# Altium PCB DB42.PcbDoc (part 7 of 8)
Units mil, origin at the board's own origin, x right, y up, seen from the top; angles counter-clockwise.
Board outline 3236.22 x 4456.69 mil, 8 copper layers (Top Layer, MidLayer1, MidLayer2, GND-Layer5, MidLayer3, VCC, MidLayer4, Bottom Layer), stack 62.194 mil thick; 214 components, 470 nets, 1802 pads, 1663 vias.
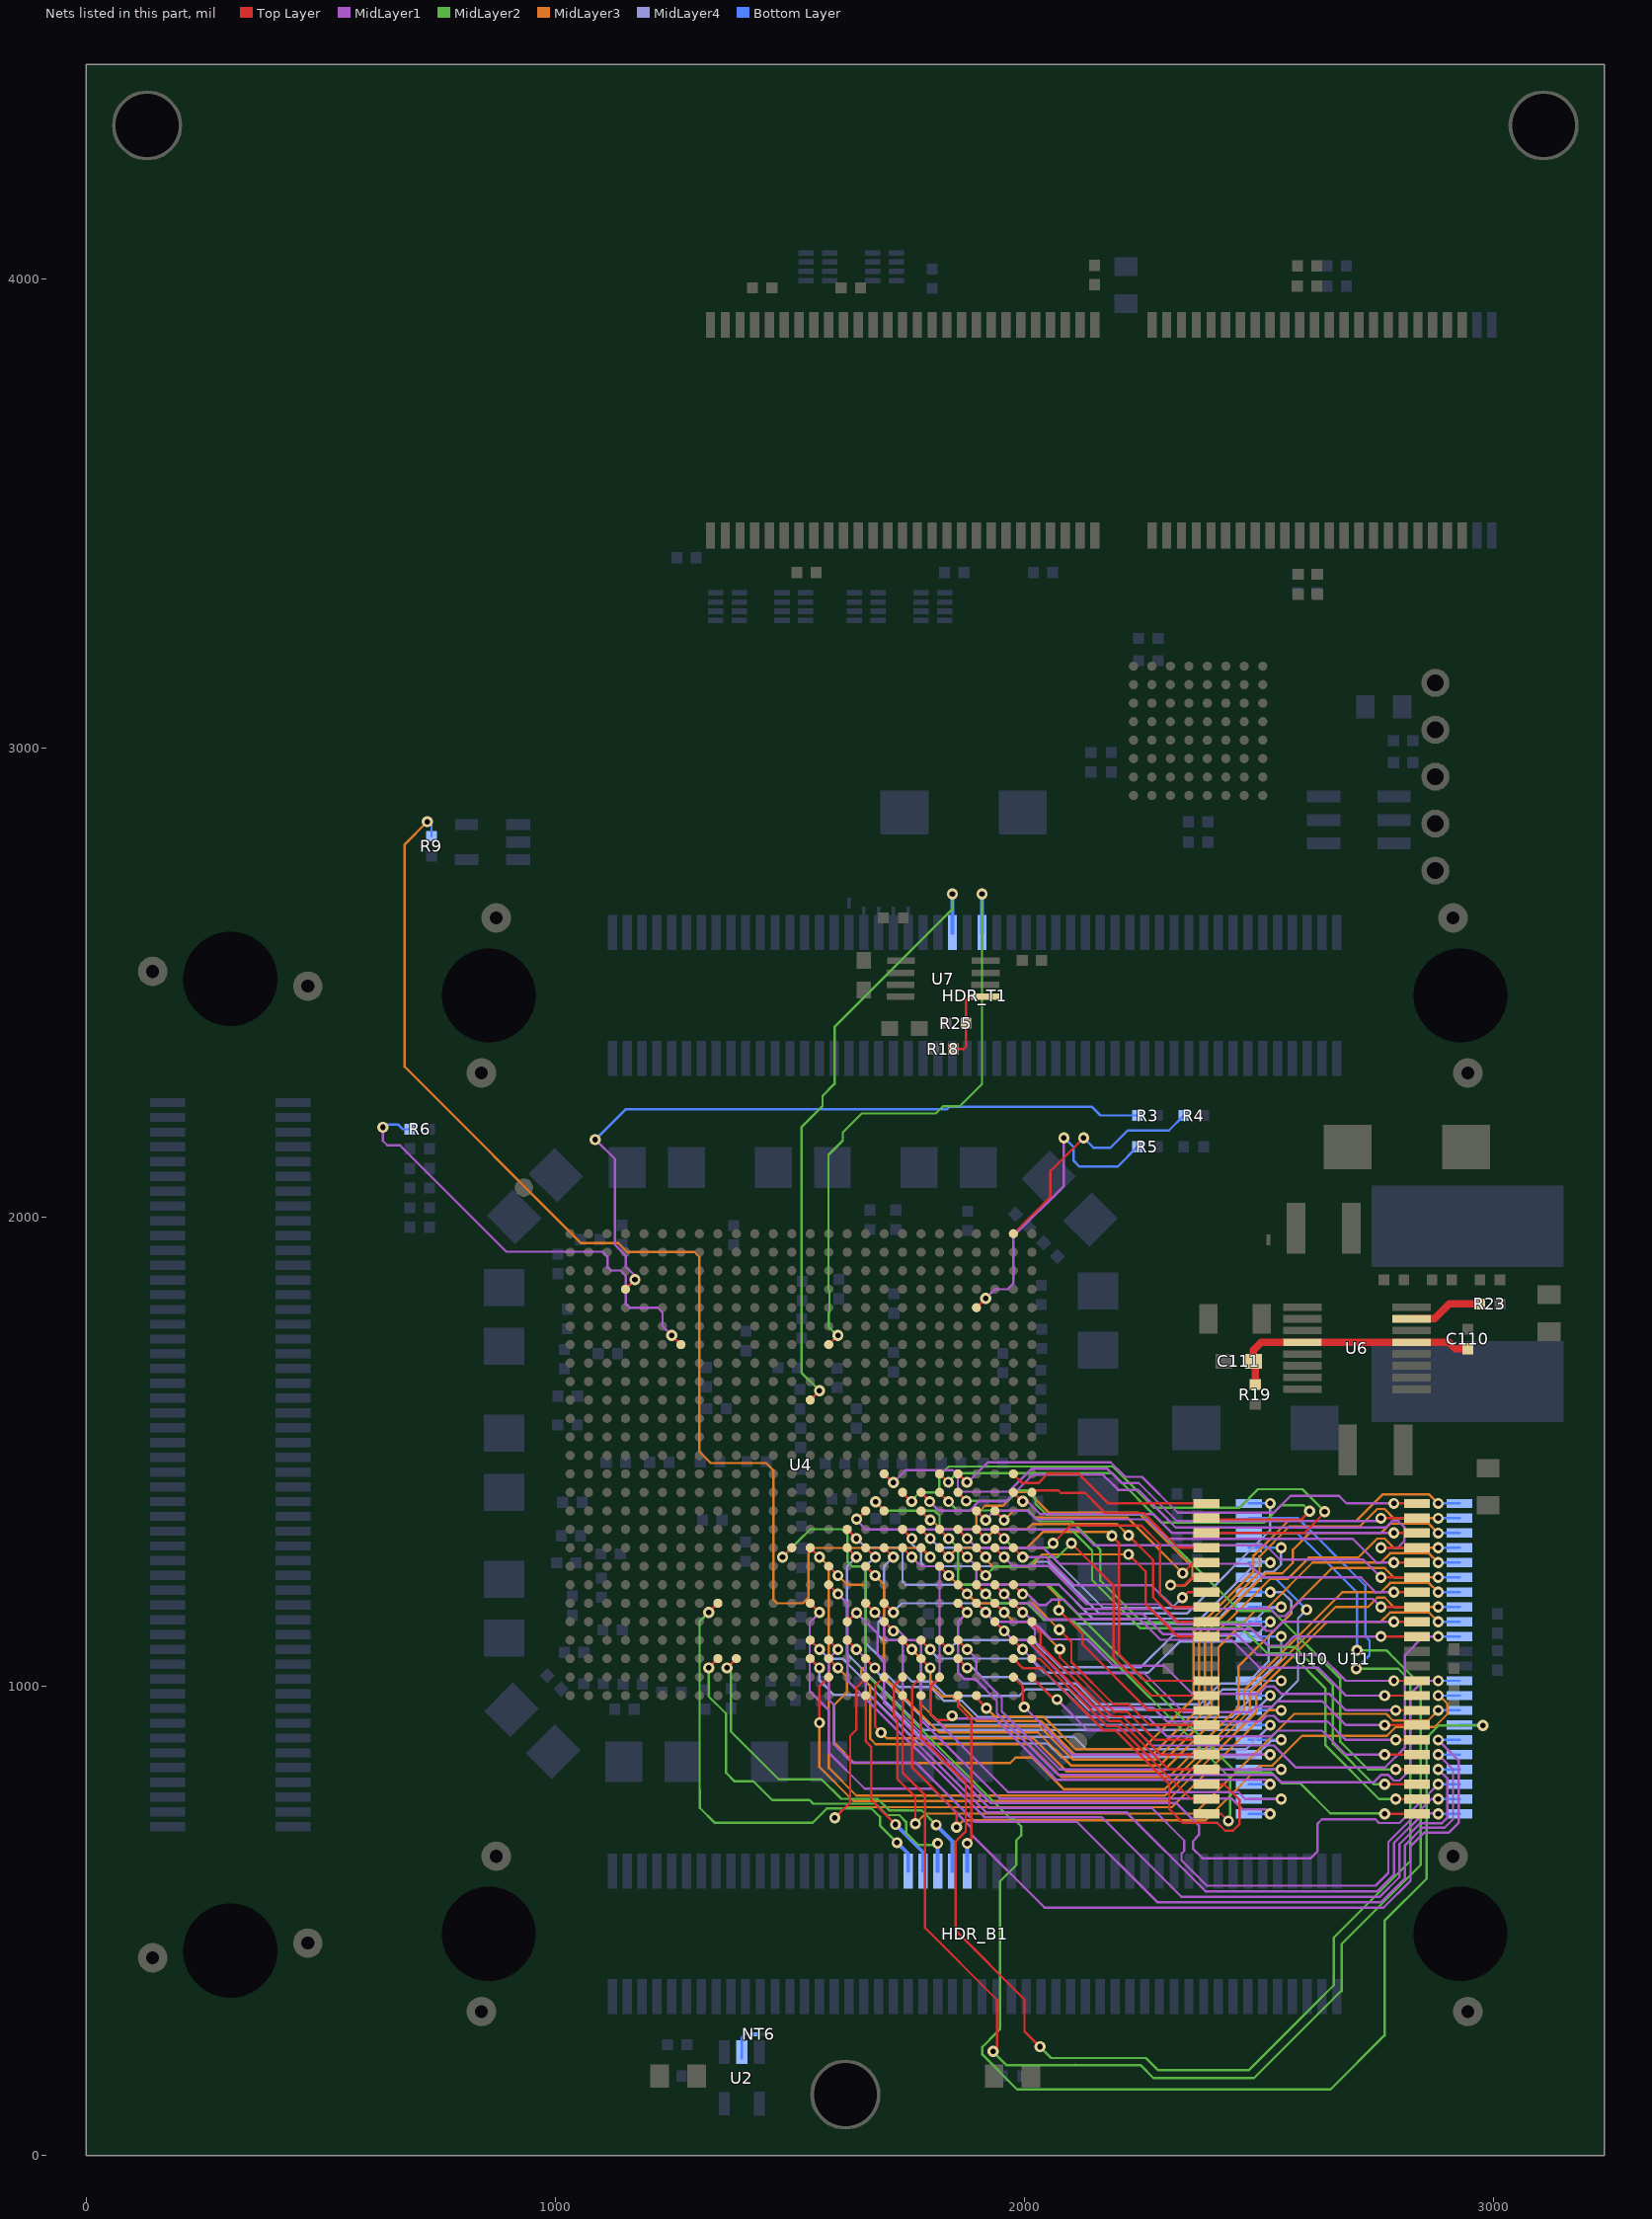
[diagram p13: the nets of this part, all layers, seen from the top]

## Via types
v1: diameter 23.62, hole 11.81, Top Layer to Bottom Layer, 1081 vias
v2: diameter 23.62, hole 11.81, Top Layer to Bottom Layer, tented both sides, 466 vias
v3: diameter 27.56, hole 15.75, Top Layer to Bottom Layer, 116 vias

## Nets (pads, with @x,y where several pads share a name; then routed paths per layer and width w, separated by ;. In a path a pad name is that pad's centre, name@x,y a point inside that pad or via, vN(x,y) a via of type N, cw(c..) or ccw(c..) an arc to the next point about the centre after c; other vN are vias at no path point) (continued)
SPI_MODE: HDR_T1.52 U4.G15 | length 1310.7
  Top Layer w5: U4.G15@1582.68,1728.35 v1(1602.36,1748.03)
  MidLayer2 w5: v1(1602.36,1748.03) 1600.52,1748.03 1592.34,1756.21 1583.05,1765.5 1583.05,1795.6 1584.24,1796.78 1584.24,1843.03 1582.3,1844.97 1582.3,2132.33 1612.78,2162.8 1612.78,2180.54 1653.12,2220.89 1811.05,2220.89 1826.28,2236.13 1861.72,2236.13 1868.9,2243.31 ; 1869.09,2243.11 1909.45,2283.47 v2(1909.45,2688.98)
  Bottom Layer w7.87: HDR_T1.52@1909.45,2606.3 v2(1909.45,2688.98)
SPI_SEL: HDR_T1.48 U4.K14 | length 1318.3
  Top Layer w5: U4.K14@1543.31,1610.24 v1(1562.99,1629.92)
  MidLayer2 w5: v1(1562.99,1629.92) 1525.2,1667.72 1525.2,2192.35 1569.44,2236.59 1569.44,2258.24 1595.06,2283.86 1595.06,2405.41 1846.46,2656.8 v2(1846.46,2688.98)
  Bottom Layer w7.87: HDR_T1.48@1846.46,2606.3 v2(1846.46,2688.98)
SRAM1_A0: U4.AB18 U11.1 | length 1130.6
  Top Layer w5: U4.AB18@1700.79,1137.8 v1(1720.47,1118.11)
  MidLayer1 w5: v1(1720.47,1118.11) 1732.28,1118.11 1751.97,1098.43 1768.11,1098.43 1779.15,1087.38 1779.15,928.72 1946.85,761.02 2441.14,761.02 2464.13,738.03 2513.94,738.03 v1(2523.62,728.35)
  Bottom Layer w5: U11.1@2478.44,728.34 v1(2523.62,728.35)
SRAM1_A1: U4.V19 U11.2 | length 1306.2
  Top Layer w5: U4.V19@1740.16,1295.28 v1(1759.84,1275.59)
  MidLayer1 w5: v1(1759.84,1275.59) 1779.53,1255.91 1812.2,1255.91 1818.9,1249.21 1818.9,1016.93 1799.7,997.74 1799.7,939.67 1964.96,774.41 2456.04,774.41 2470.61,759.84 v1(2547.24,759.84)
  Bottom Layer w5: U11.2@2478.44,759.83 v1(2547.24,759.84)
SRAM1_A2: U4.AE21 U11.3 | length 926
  Top Layer w5: U4.AE21@1818.9,1019.68 1818.9,1018.9 1799.13,999.13 1799.13,941.42 1812.49,928.06 1836.32,928.06 v1(1845.61,937.34)
  MidLayer1 w5: v1(1845.61,937.34) 1851.46,931.5 1936.63,931.5 2067.1,801.02 2513.94,801.02 v1(2523.62,791.34)
  Bottom Layer w5: U11.3@2478.44,791.33 v1(2523.62,791.34)
SRAM1_A3: U4.AC22 U11.4 | length 906.3
  Top Layer w5: U4.AC22@1858.27,1098.42 v1(1877.95,1078.74)
  MidLayer1 w5: v1(1877.95,1078.74) 1897.26,1059.43 1897.26,1029.53 1951.57,975.22 1951.57,946.46 2075.2,822.83 v1(2547.24,822.83)
  Bottom Layer w5: U11.4@2478.44,822.83 v1(2547.24,822.83)
SRAM1_A4: U4.AE25 U11.5 | length 684.7
  Top Layer w5: U4.AE25@1976.38,1019.68 1996.46,999.61 1996.46,959.06 v1(1999.61,955.91)
  MidLayer1 w5: v1(1999.61,955.91) 2101.18,854.33 v1(2523.62,854.33)
  Bottom Layer w5: U11.5@2478.44,854.32 v1(2523.62,854.33)
SRAM1_A5: U4.U16 U11.18 | length 1110.9
  Top Layer w5: U4.U16@1622.05,1334.65 v1(1641.73,1314.96)
  MidLayer4 w5: v1@1642.52,1314.96 1662.2,1295.28 1731.89,1295.28 1740.16,1287.01 1740.16,1223.23 1746.85,1216.54 2072.98,1216.54 2145.16,1144.35 2375.45,1144.35 2496.85,1265.75 v1@2521.85,1265.75
  Bottom Layer w5: U11.18@2478.44,1263.77 v1(2523.83,1263.77)
SRAM1_A6: U4.AA18 U11.19 | length 1037.2
  Top Layer w5: U4.AA18@1700.79,1177.17 v1(1720.47,1157.48)
  MidLayer4 w5: v1@1719.68,1158.27 1738.58,1177.17 2006.07,1177.17 2040.82,1142.42 ; 2040.82,1141.44 2096.9,1141.44 2104.78,1133.57 2403.91,1133.57 2420.64,1150.3 ; 2420.11,1150.82 2453.95,1184.66 2513.61,1244.32 2531.72,1244.32 2546.85,1259.45 v1@2546.85,1294.88
  Bottom Layer w5: U11.19@2478.44,1295.27 v1(2547.24,1295.28)
SRAM1_A7: U4.AF19 U11.20 | length 2986.5
  Top Layer w5: U4.AF19@1740.16,980.31 1740.16,815.75 1788.19,767.72 1788.19,485.04 1941.73,331.5 1941.73,230.71 v1(1933.07,222.05)
  MidLayer2 w5: v1@1932.28,222.44 1932.28,222.05 1932.28,221.65 1932.48,221.46 1961.02,192.91 2107.87,192.91 ; 2108.27,193.31 2107.87,192.91 ; 2675.98,350.39 2675.98,351.97 ; v1(2708.66,1076.77) 2771.26,1076.77 2788.34,1059.69 2844.49,1003.54 2844.49,825.98 ; 2844.09,826.38 2844.49,825.98 ; 2107.87,192.91 2247.24,192.91 2274.8,165.35 2489.37,165.35 2675.98,351.97 ; 2675.98,351.97 2675.98,450.79 2844.49,619.29 2844.49,825.98
  Bottom Layer w5: U11.20@2478.44,1326.76 2581.51,1326.76 2603.35,1304.92 ; 2603.54,1305.12 2708.66,1200 v1(2708.66,1076.77)
SRAM1_A8: U4.AF20 U11.21 | length 2934.3
  Top Layer w5: U4.AF20@1779.53,980.31 1779.53,890.55 1857.87,812.2 ; 1857.87,811.42 1872.44,796.85 ; 1872.83,796.85 1874.85,794.83 1874.85,690.6 1862.2,677.95 1853.54,669.29 1853.54,479.13 2000,332.68 2000,264.96 v1(2032.94,232.02)
  MidLayer2 w5: v1(2032.94,232.02) 2057.09,207.87 2258.66,207.87 2284.25,182.28 2478.74,182.28 2620.95,324.49 2659.45,362.99 2659.45,464.57 2822.44,627.56 2822.44,1011.45 2816.16,1017.73 2796.06,1037.8 v1(2707.09,1037.8)
  Bottom Layer w5: U11.21@2478.44,1358.26 2583.07,1358.27 2642.91,1298.43 2658.02,1283.32 2726.77,1214.57 2726.77,1106.69 2729.53,1103.94 2735.71,1097.75 2735.71,1066.42 v1(2707.09,1037.8)
SRAM1_A9: U4.U19 U11.22 | length 1061
  Top Layer w5: U4.U19@1740.16,1334.65 v1(1759.84,1314.96)
  MidLayer4 w5: v1@1759.84,1316.14 v1(1759.84,1314.96) 1759.84,1303.39 1779.53,1283.71 1779.53,1262.99 1786.61,1255.91 2014.57,1255.91 2024.09,1265.42 2049.2,1265.42 2159.45,1155.18 2346.12,1155.18 2523.23,1332.28 v1@2523.23,1389.15
  Bottom Layer w5: U11.22@2478.44,1389.75 v1(2523.83,1389.75)
SRAM1_A10: U4.AF23 U11.23 | length 1416.3
  Top Layer w5: U4.AF23@1897.64,980.31 1897.64,974.8 v1(1918.9,953.54)
  MidLayer3 w5: v1(1918.9,953.54) 1936.61,935.83 2039.83,935.83 2109.52,866.14 2251.58,866.14 2360.63,975.2 2360.63,1117.29 2488.04,1244.7 2488.04,1278.3 2562.4,1352.66 2707.38,1352.66 2764.17,1409.45 2862.2,1409.45 v1(2881.9,1389.75)
  Bottom Layer w5: v1(2881.9,1389.75) U11.23@2927.25,1389.75
SRAM1_A11: U4.AD20 U11.24 | length 1592.3
  Top Layer w5: U4.AD20@1779.53,1059.05 v1(1799.21,1039.37)
  MidLayer3 w5: v1(1799.21,1039.37) 1799.21,1003.54 1824.02,978.74 1845.67,978.74 1898.58,925.83 2035.69,925.83 2105.37,856.14 2106.56,856.14 2107.98,854.72 2273.62,854.72 2372.05,953.15 2372.05,1114.57 2500.79,1243.31 2500.79,1276.38 ; 2500.63,1276.54 2564.64,1340.55 2714.57,1340.55 2751.97,1377.95 2767.72,1377.95 2787.41,1358.26 v1(2881.9,1358.26)
  Bottom Layer w5: v1(2881.9,1358.26) U11.24@2927.25,1358.26
SRAM1_A12: U4.AC19 U11.25 | length 1677.4
  Top Layer w5: U4.AC19@1740.16,1098.42 v1(1759.84,1078.74)
  MidLayer3 w5: v1(1759.84,1078.74) 1761.42,1077.17 1779.53,1059.06 1779.53,962 1827.35,914.17 2033.2,914.17 2101.23,846.14 2101.86,846.14 2103.91,844.09 2280.71,844.09 2384.65,948.03 2384.65,1111.02 2514.57,1240.94 2550,1240.94 2572.05,1262.99 2572.05,1290.95 2607.48,1326.38 2759.45,1326.38 2779.53,1346.46 2862.2,1346.46 v1(2881.9,1326.76)
  Bottom Layer w5: v1(2881.9,1326.76) U11.25@2927.25,1326.76
SRAM1_A13: U4.W17 U11.26 | length 1862.4
  Top Layer w5: U4.W17@1661.42,1255.91 v1(1681.5,1236.22)
  MidLayer3 w5: v1@1679.92,1237.01 1680.31,1237.01 1681.3,1236.02 1700.79,1216.54 1700.79,1019 1817.82,901.97 2029.03,901.97 2099.9,831.1 2287.4,831.1 2398.82,942.52 2398.82,1103.94 2523.62,1228.74 2560.63,1228.74 2605.91,1274.02 2711.02,1274.02 2751.97,1314.96 2767.72,1314.96 2787.41,1295.27 v1(2881.9,1295.27)
  Bottom Layer w5: v1(2881.9,1295.27) U11.26@2927.25,1295.27
SRAM1_A14: U4.AE18 U11.27 | length 1685.3
  Top Layer w5: v1(1694.45,901.34) 1681.46,914.34 1681.46,1000.71 1700.43,1019.68 U4.AE18@1700.79,1019.68
  MidLayer3 w5: v1(1694.45,901.34) 1706.28,889.51 2018.49,889.51 2089.1,818.9 2295.67,818.9 2413.58,936.81 2413.58,1083.27 2496.46,1166.14 2516.54,1166.14 2614.17,1263.78 2759.84,1263.78 2779.53,1283.46 2862.2,1283.46 v1(2881.9,1263.77)
  Bottom Layer w5: v1(2881.9,1263.77) U11.27@2927.25,1263.77
SRAM1_A15: U4.AA17 U11.42 | length 1750
  Top Layer w5: U4.AA17@1661.42,1177.17 v1(1681.1,1157.48)
  MidLayer1 w5: v1(1681.1,1157.48) 1700.41,1138.17 1700.41,1107.46 1709.82,1098.05 1732.27,1098.05 1740.53,1089.78 1740.53,938.84 1928.35,751.02 2323.78,751.02 2371.65,703.15 2371.65,683.19 2365.8,677.33 2365.8,676.03 2359.06,669.29 2359.06,654.33 2379.53,633.86 2610.24,633.86 2624.26,647.88 2624.26,706.94 2633.86,716.54 2748.03,716.54 2755.91,708.66 2799.21,708.66 v1(2881.9,791.33)
  Bottom Layer w5: v1(2881.9,791.33) U11.42@2927.25,791.33
SRAM1_A16: U4.AB16 U11.43 | length 1781.7
  Top Layer w5: U4.AB16@1622.05,1137.8 1622.44,1137.8 1641.73,1157.09 v1@1642.52,1157.87
  MidLayer1 w5: v1(1642.13,1156.69) 1642.52,1156.69 1686.61,1112.6 1686.61,1068.5 1700.79,1054.33 1700.79,964.31 1924.07,741.02 2270.88,741.02 2340.55,671.35 2340.55,649.21 2334.65,643.31 2334.65,629.13 2388.73,575.05 2748.28,575.05 2775.59,602.36 2775.59,668.39 2867.03,759.83 v1(2881.9,759.83)
  Bottom Layer w5: v1(2881.9,759.83) U11.43@2927.25,759.83
SRAM1_A17: U4.AC16 U11.44 | length 1675.8
  Top Layer w5: U4.AC16@1622.05,1098.42 v1(1641.73,1078.74)
  MidLayer1 w5: v1(1641.73,1078.74) 1661.79,1058.68 1661.79,988.21 1918.98,731.02 2217.98,731.02 2385.76,563.24 2752.21,563.24 2787.4,598.43 2787.4,666.06 2850.28,728.93 v1@2881.3,728.93
  Bottom Layer w5: v1(2881.9,728.34) U11.44@2927.25,728.34
SRAM1_A18: U4.W15 U11.28 | length 1971.8
  Top Layer w5: U4.W15@1582.68,1255.91 v1(1602.36,1236.22)
  MidLayer3 w5: v1(1602.36,1236.22) 1622.05,1216.54 1655.91,1216.54 1661.42,1211.02 1661.42,1157.56 1661.79,1157.19 1661.79,1044.08 1651.97,1034.25 1651.97,1021 1671,1001.97 1671,888.38 1682.68,876.7 2008.38,876.7 2078.21,806.88 2307.67,806.88 2455.91,955.12 2455.91,1042.52 2567.72,1154.33 2567.72,1164.57 2655.12,1251.97 2767.72,1251.97 2787.41,1232.28 v1(2881.9,1232.27)
  Bottom Layer w5: v1(2881.9,1232.27) U11.28@2927.25,1232.27
SRAM1_D0: U4.AC14 U11.7 | length 1144.9
  Top Layer w5: U4.AC14@1543.31,1098.42 v1(1562.99,1078.74)
  MidLayer4 w5: v1(1562.99,1078.74) 1582.99,1058.74 1612.82,1058.74 1779.07,892.49 2105.76,892.49 2132.08,866.17 2472.69,866.17 v1(2523.83,917.3) v1@2524.99,916.14
  Bottom Layer w5: U11.7@2478.44,917.31 v1(2523.83,917.3)
SRAM1_D1: U4.AE17 U11.8 | length 1441.3
  Top Layer w5: v1(1595.67,719.68) 1605.49,729.51 1628.52,752.54 1628.52,894.52 1641.54,907.54 1641.54,997.32 U4.AE17@1662.28,1018.07
  MidLayer3 w5: v1(1595.67,719.68) 1618.5,742.52 2314.17,742.52 2520.47,948.82 v1(2547.24,948.82)
  Bottom Layer w5: U11.8@2478.44,948.81 v1(2547.24,948.82)
SRAM1_D2: U4.AD17 U11.9 | length 994.7
  Top Layer w5: U4.AD17@1661.42,1059.05 v1(1681.1,1039.37)
  MidLayer4 w5: v1(1681.1,1039.37) 1681.1,1034.74 1797.81,918.03 2461.56,918.03 v1(2523.83,980.31)
  Bottom Layer w5: U11.9@2478.44,980.31 v1(2523.83,980.31)
SRAM1_D3: U4.V17 U11.10 | length 1288.6
  Top Layer w5: U4.V17@1661.42,1295.28 v1@1681.1,1275.59
  MidLayer4 w5: v1@1681.1,1275.59 1661.42,1255.91 1661.42,1157.56 1661.79,1157.19 1661.79,1091.75 1689.4,1064.14 1700.79,1052.76 1700.79,1030.25 1710.9,1020.13 ; 1711.18,1020.41 1732.82,998.76 1798.75,998.76 1828.27,969.24 1866.65,969.24 1901.71,934.18 2442.45,934.18 2461.23,952.96 2520.08,1011.81 v1(2547.24,1011.81)
  Bottom Layer w5: U11.10@2478.44,1011.8 v1(2547.24,1011.81) v1@2551.18,1011.81
  other v1: 1682.28,1275.59
SRAM1_D4: U4.V18 U11.13 | length 1342.9
  Top Layer w5: U4.V18@1700.79,1295.28 v1(1720.47,1275.59)
  MidLayer4 w5: v1(1720.47,1275.59) 1707.75,1262.87 1700.81,1255.92 1700.81,1149.63 1688.58,1137.4 1688.58,1108.66 1698.82,1098.43 1731.1,1098.43 1740.16,1089.37 1740.16,1030.32 1742.58,1027.89 1760.54,1009.93 1802.39,1009.93 1832.3,980.02 1989.08,980.02 2002.36,993.31 2094.69,993.31 2138,950 2378.69,950 2422,993.31 2481.1,993.31 2547.24,1059.45 v1(2547.24,1106.3)
  Bottom Layer w5: U11.13@2478.44,1106.29 v1(2547.24,1106.3) v1@2551.18,1106.3
SRAM1_D5: U4.AC20 U11.14 | length 870.1
  Top Layer w5: U4.AC20@1779.53,1098.42 v1(1799.21,1078.74)
  MidLayer4 w5: v1@1798.43,1079.92 1798.43,1078.74 1798.43,1077.17 1816.54,1059.06 2012.6,1059.06 2042.39,1029.26 2264.1,1029.26 2330.11,1095.28 2481.32,1095.28 v1(2523.83,1137.79)
  Bottom Layer w5: U11.14@2478.44,1137.79 v1(2523.83,1137.79) v1@2527.77,1137.79
SRAM1_D6: U4.AC21 U11.15 | length 889.9
  Top Layer w5: U4.AC21@1818.9,1098.42 v1(1838.58,1078.74)
  MidLayer4 w5: v1@1838.98,1078.74 1858.66,1098.43 2017.72,1098.43 2075.07,1041.07 2248.16,1041.07 2315.35,1108.27 2459.06,1108.27 2518.11,1167.32 2545.28,1167.32 v1(2547.24,1169.29)
  Bottom Layer w5: U11.15@2478.44,1169.28 v1(2547.24,1169.29)
SRAM1_D7: U4.AD22 U11.16 | length 992.6
  Top Layer w5: U4.AD22@1858.27,1059.05 v1(1877.95,1039.37)
  MidLayer4 w5: v1@1876.38,1039.76 1877.95,1039.76 1889.31,1039.76 1909.39,1019.68 1982.68,1019.68 1996.46,1005.91 2109.09,1005.91 2153,962 2374.09,962 2418,1005.91 2473.23,1005.91 2520.08,1052.76 2520.08,1106.69 2548.82,1135.43 2548.82,1135.83 2569.01,1156.02 2569.01,1180.99 2549.21,1200.79 v1@2523.84,1200.79
  Bottom Layer w5: U11.16@2478.44,1200.78 v1(2523.83,1200.78) v1@2527.77,1200.78
SRAM1_D8: U4.AD15 U11.29 | length 1804.8
  Top Layer w5: U4.AD15@1582.68,1059.05 v1(1602.36,1039.37)
  MidLayer3 w5: v1(1602.36,1039.37) 1621.71,1020.02 1621.71,987.85 1610.24,976.38 1594.49,960.63 1594.49,879.29 1637.42,836.36 1968.94,836.36 1980.79,848.21 2016.22,848.21 2083.32,781.1 2299.24,781.1 2468.41,950.26 2468.41,991.63 2677.56,1200.79 2759.84,1200.79 2779.53,1220.47 2862.2,1220.47 v1(2881.9,1200.78)
  Bottom Layer w5: v1(2881.9,1200.78) U11.29@2927.25,1200.78
SRAM1_D9: U4.V14 U11.30 | length 2059.7
  Top Layer w5: U4.V14@1543.31,1295.28 v1(1562.99,1275.59)
  MidLayer3 w5: v1(1562.99,1275.59) 1582.68,1255.91 1582.68,826.32 1641.68,767.32 2299.61,767.32 2480.31,948.03 2480.31,986.62 2662.99,1169.29 2732.28,1169.29 2751.97,1188.98 2767.72,1188.98 2787.41,1169.29 v1(2881.9,1169.28)
  Bottom Layer w5: v1(2881.9,1169.28) U11.30@2927.25,1169.28
SRAM1_D10: U4.AE15 U11.31 | length 1793.4
  Top Layer w5: v1(1562.99,922.44) 1562.99,1000 U4.AE15@1582.54,1019.55 ; U4.AE15@1582.4,1019.68 U4.AE15@1582.54,1019.55 ; U4.AE15@1582.68,1019.68 U4.AE15@1582.54,1019.55
  MidLayer3 w5: v1@1563.19,922.24 v1(1562.99,922.44) 1562.99,828.01 1635.49,755.51 2304.72,755.51 2493.7,944.49 2493.7,985.73 2645.77,1137.8 2759.84,1137.8 2779.53,1157.48 2862.2,1157.48 v1(2881.9,1137.79)
  Bottom Layer w5: v1(2881.9,1137.79) U11.31@2927.25,1137.79
SRAM1_D11: U4.AE26 U11.32 | length 1226.8
  Top Layer w5: U4.AE26@2015.75,1019.68 2063.46,971.97 v1(2069.49,971.97)
  MidLayer1 w5: v1(2069.49,971.97) 2135.33,906.13 2239.54,906.13 2271.65,874.02 2531.5,874.02 2578.75,826.76 2767.71,826.76 2811.02,870.08 2811.02,1066.93 2850.39,1106.3 2858.27,1106.3 2862.59,1106.3 ; 2858.28,1106.29 v1(2881.9,1106.29)
  Bottom Layer w5: v1(2881.9,1106.29) U11.32@2927.25,1106.29
SRAM1_D12: U4.AA22 U11.35 | length 1539.8
  Top Layer w5: U4.AA22@1858.27,1177.17 v1(1877.95,1157.48)
  MidLayer1 w5: v1(1877.95,1157.48) 1858.64,1138.17 1858.64,1028.74 1871.64,1015.75 1894.49,1015.75 1940.94,969.29 1940.94,942.18 2072.1,811.02 2531.5,811.02 2547.24,795.28 2744.09,795.27 2759.84,811.02 2775.6,811.02 2787.4,799.21 2799.21,799.21 2822.83,822.83 2822.83,984.25 2850.39,1011.81 2862.2,1011.81 ; 2862.21,1011.8 v1(2881.9,1011.8)
  Bottom Layer w5: v1(2881.9,1011.8) U11.35@2927.25,1011.8
SRAM1_D13: U4.AE20 U11.36 | length 1606.8
  Top Layer w5: U4.AE20@1779.53,1019.68 1779.53,1018.94 1760.28,999.68 1760.28,827.37 1855.36,732.28 v1(1855.36,699.76)
  MidLayer3 w5: v1(1855.36,699.76) 1869.77,714.17 2385.83,714.17 2461.61,789.96 ; 2461.42,790.16 2501.97,830.71 2526.77,830.71 ; 2527.17,830.32 2591.34,894.49 2772.44,894.49 2791.34,913.39 2874.01,913.39 2901.45,940.82 2901.45,963.12 v1@2883.08,981.49
  Bottom Layer w5: v1(2881.9,980.31) U11.36@2927.25,980.31
SRAM1_D14: U4.AE19 U11.37 | length 1611.2
  Top Layer w5: 1721.16,1000.49 1740.16,1019.49 U4.AE19@1740.16,1019.68 ; 1721.26,1000.39 1721.26,935.43 1729.13,927.56 1729.13,802.36 1767.32,764.17 v1(1767.32,707.09)
  MidLayer3 w5: v1(1767.32,707.09) 1788.98,728.74 2362.6,728.74 2575.2,941.34 2771.26,941.34 2785.43,927.17 2860.26,927.17 v1(2881.9,948.81)
  Bottom Layer w5: v1(2881.9,948.81) U11.37@2927.25,948.81
SRAM1_D15: U4.V13 U11.38 | length 3294.1
  Top Layer w5: v1(1484.25,1275.59) U4.V13@1503.94,1295.28
  MidLayer2 w5: v1(1484.25,1275.59) 1517.25,1308.59 1543.68,1335.02 1610.24,1335.02 1622.42,1322.83 1622.42,1266.18 1633.07,1255.53 1651.16,1255.53 1661.97,1244.72 1661.97,1230.48 1661.02,1229.53 1661.02,1196.15 1661.85,1195.32 1661.85,1174.02 ; 1661.79,1173.96 1661.79,1026.21 1970.28,717.72 1977.17,717.72 1993.31,701.57 1993.31,682.28 1982.68,671.65 1982.68,619.29 1948.03,584.65 1948.03,269.29 1940.17,261.43 1910.24,231.5 1910.24,214.96 1984.25,140.94 2652.36,140.94 2767.32,255.91 2767.32,500.1 2857.48,590.26 2857.48,890.94 2870.54,904 2883.07,916.54 v1(2977.17,916.54)
  Bottom Layer w5: U11.38@2927.25,917.31 v1@2976.39,917.31
SRAM1_NBHE: U4.AC15 U11.40 | length 2012.8
  Top Layer w5: U4.AC15@1582.68,1098.42 v1(1602.36,1078.74)
  MidLayer1 w5: v1(1602.36,1078.74) 1582.68,1059.05 1582.68,971.79 1593.1,961.37 1593.1,876.74 1632.46,837.38 1768.25,837.38 1894.61,711.02 2111.98,711.02 2282.89,540.11 2760.58,540.11 2811.02,590.55 2811.02,661.4 2848.23,698.6 2895.45,698.6 2913.39,716.54 2913.39,822.83 v1(2881.9,854.32)
  Bottom Layer w5: v1(2881.9,854.32) U11.40@2927.25,854.32
SRAM1_NBLE: U4.AA14 U11.39 | length 2198.7
  Top Layer w5: U4.AA14@1543.31,1177.17 v1(1562.99,1157.48)
  MidLayer1 w5: v1@1564.17,1157.48 1563.58,1156.89 1542.13,1135.43 1542.13,990.05 1582.36,949.82 1582.36,858.95 1659.41,781.89 1804.06,781.89 1886.61,699.34 1886.61,684.39 2042.46,528.54 2765.75,528.54 2822.83,585.63 2822.83,659.07 2852.37,688.6 2905.14,688.6 2925.2,708.66 2925.2,842.52 v1(2881.9,885.82)
  Bottom Layer w5: v1(2881.9,885.82) U11.39@2927.25,885.82
SRAM1_NCS: U4.AD14 U11.6 | length 1194.4
  Top Layer w5: U4.AD14@1543.31,1059.05 v1(1562.99,1039.37)
  MidLayer4 w5: v1(1562.99,1039.37) 1562.99,1012.71 1594.23,981.47 1670.41,981.47 1773.61,878.27 2049.73,878.27 2078.81,849.19 2490.63,849.19 2524.9,883.46 2544.88,883.46 v1(2547.24,885.83)
  Bottom Layer w5: U11.6@2478.44,885.82 v1(2547.24,885.83) v1@2551.18,885.83
SRAM1_NOE: U4.Y15 U11.41 | length 1957.1
  Top Layer w5: U4.Y15@1582.68,1216.54 v1(1602.36,1196.85)
  MidLayer1 w5: v1(1602.36,1196.85) 1622.42,1176.79 1622.42,1013.01 1914.41,721.02 2164.58,721.02 2333.93,551.67 2757.38,551.67 2799.21,593.5 2799.21,663.73 2844.08,708.6 2889.7,708.6 2901.57,720.47 2901.57,803.15 v1(2881.9,822.83)
  Bottom Layer w5: v1(2881.9,822.83) U11.41@2927.25,822.83
SRAM1_NWE: U4.V16 U11.17 | length 1624.4
  Top Layer w5: U4.V16@1622.05,1295.28 v1(1641.73,1275.59)
  MidLayer4 w5: v1(1641.73,1275.59) 1622.05,1255.9 1622.05,1069.19 1783.92,907.32 2478.18,907.32 2501.61,930.74 2543.7,972.83 2583.07,1012.2 2583.07,1144.88 v1(2601.57,1163.39)
  Bottom Layer w5: U11.17@2478.44,1232.28 2479.24,1231.83 2533.13,1231.83 v1(2601.57,1163.39)
SRAM2_A0: U4.U21 U10.1 | length 1308.7
  Top Layer w5: U4.U21@1818.9,1334.65 v1(1838.58,1314.96) ; v1(2767.69,728.34) U10.1@2836.71,728.34
  MidLayer2 w5: v1@1839.76,1313.78 1858.26,1295.27 1858.26,1224.61 1866.65,1216.22 2051.64,1216.22 2450.97,816.9 2525.75,816.9 2549.54,793.1 2587.92,793.1 2651.92,729.1 2766.93,729.1 v1(2767.69,728.34)
SRAM2_A1: U4.T18 U10.2 | length 1563.2
  Top Layer w5: v1(1682.68,1393.31) 1700.79,1375.2 U4.T18@1700.79,1374.02 ; v1(2791.34,759.84) U10.2@2836.71,759.83
  MidLayer2 w5: v1(1682.68,1393.31) 1701.97,1374.02 1808.66,1374.02 1818.9,1363.78 1818.9,1342.52 1826.77,1334.64 2098.87,1334.64 2144.14,1289.38 2144.14,1227.05 2247.56,1123.62 2464.14,1123.62 2517.66,1070.1 2566.91,1070.1 2641.73,995.28 2641.73,874.02 2755.91,759.84 v1(2791.34,759.84)
SRAM2_A2: U4.R21 U10.3 | length 1384.3
  Top Layer w5: U4.R21@1818.9,1413.39 1818.9,1412.2 v1@1835.83,1395.28 ; v1(2767.69,791.34) U10.3@2836.71,791.33
  MidLayer2 w5: v1(1838.19,1393.7) 1857.09,1374.8 2008.22,1374.8 2031.21,1351.81 2100.84,1351.81 2161.85,1290.81 2161.85,1225.08 2250.45,1136.48 2469.41,1136.48 2521.99,1083.89 2575.58,1083.89 2657.48,1001.99 2657.48,877.95 2744.1,791.34 v1(2767.69,791.34)
SRAM2_A3: U4.R22 U10.4 | length 1327.1
  Top Layer w5: U4.R22@1858.27,1413.39 1858.27,1412.6 v1@1875.59,1395.28 ; v1(2791.34,822.83) U10.4@2836.71,822.83
  MidLayer2 w5: v1(1875.71,1395.15) 1964.45,1395.15 1986.61,1417.32 2007.48,1417.32 2023.23,1401.57 2023.23,1389.76 2046.85,1366.14 2253.54,1366.14 2345.5,1274.19 2458.98,1160.7 2528.32,1160.7 2673.23,1015.79 2673.23,881.89 2732.28,822.83 v1(2791.34,822.83)
SRAM2_A4: U4.AC25 U10.5 | length 963.4
  Top Layer w5: U4.AC25@1976.38,1098.42 v1(1996.06,1078.74) ; v1(2767.69,854.33) U10.5@2836.71,854.32
  MidLayer1 w5: v1(1996.06,1078.74) 2138.63,936.17 2260.68,936.17 2303.15,893.7 2527.56,893.7 2539.37,905.51 2633.86,905.51 2685.04,854.33 v1@2759.84,854.31
SRAM2_A5: U4.T23 U10.18 | length 1001.7
  Top Layer w5: U4.T23@1897.64,1374.02 v1(1917.32,1354.33) ; v1@2787.4,1263.77 U10.18@2836.71,1263.77
  MidLayer1 w5: v1(1917.32,1354.33) 1917.32,1355.51 1935.83,1374.02 2006.69,1374.02 2024.8,1355.91 2262.2,1355.91 2303.49,1314.62 2699.44,1314.62 2750.28,1263.78 v1(2787.4,1263.78)
SRAM2_A6: U4.R20 U10.19 | length 1297.3
  Top Layer w5: U4.R20@1779.53,1413.39 1779.53,1412.99 v1@1796.85,1395.67 ; v1(2759.84,1295.28) U10.19@2836.71,1295.27
  MidLayer1 w5: v1(1798.03,1393.7) 1817.73,1374 1882.68,1374 1903.39,1394.71 1961.64,1394.71 2018.49,1451.56 2166.15,1451.56 2176.38,1441.34 ; 2176.77,1441.73 2199.61,1418.9 2241.73,1418.9 2307.08,1353.55 2322.44,1338.2 2769.7,1338.2 2783.46,1351.97 2797.24,1351.97 2809.84,1339.37 2809.84,1309.45 2795.67,1295.28 v1(2759.84,1295.28)
SRAM2_A7: U4.R25 U10.20 | length 896.6
  Top Layer w5: U4.R25@1975.98,1413.39 U4.R25@1975.98,1413.78 ; U4.R25@1976.38,1413.39 1976.38,1412.6 1995.47,1393.5 v1@1995.67,1393.31 ; v1(2787.4,1326.77) U10.20@2836.71,1326.76
  MidLayer1 w5: v1@1996.65,1394.29 1996.58,1394.22 2006.18,1394.22 2033.07,1367.32 2274.41,1367.32 2314.96,1326.77 v1(2787.4,1326.77)
  other v1: 1996.46,1394.49
SRAM2_A8: U4.P18 U10.21 | length 1259.2
  Top Layer w5: U4.P18@1700.79,1452.76 v1@1720.47,1433.07 ; v1(2759.84,1358.27) U10.21@2836.71,1358.26
  MidLayer1 w5: v1(1720.47,1434.25) 1747.22,1461 1847,1461 1858,1450 1858,1423 1866.07,1414.93 1966.51,1414.93 2015.75,1464.17 2175.98,1464.17 2205.38,1434.78 2206.69,1433.46 2243.7,1433.46 2266.93,1410.24 2324.8,1352.36 2753.94,1352.36 v1(2759.84,1358.27)
SRAM2_A9: U4.P22 U10.22 | length 1070.9
  Top Layer w5: U4.P22@1858.27,1452.76 v1(1877.56,1435.04) ; v1(2787.4,1389.76) U10.22@2836.71,1389.76
  MidLayer1 w5: v1@1876.77,1432.28 1878.54,1434.06 1922.05,1477.56 2183.5,1477.56 2208.48,1452.58 2214.57,1446.49 2250.36,1446.49 2326.77,1370.08 2531.5,1370.08 2567.32,1405.91 2670.47,1405.91 2686.61,1389.76 v1(2787.4,1389.76)
SRAM2_A10: U4.P25 U10.23 | length 454.4
  Top Layer w5: U4.P25@1976.38,1452.76 1976.38,1452.21 1995.61,1432.98 2029.13,1432.98 2049.06,1452.9 2116.05,1452.9 2179.2,1389.76 U10.23@2387.89,1389.76
SRAM2_A11: U4.P21 U10.24 | length 1096.4
  Top Layer w5: U4.P21@1818.9,1452.76 v1(1837.8,1435.04) v1@1838.98,1433.86 ; U10.24@2389.76,1355.91 2590.63,1355.91 v1@2607.72,1372.99
  MidLayer2 w5: v1@1838.98,1433.86 1838.98,1435.04 1838.98,1437.1 1856.51,1454.63 2186.71,1454.63 2292.52,1348.82 2510.24,1348.82 2547.24,1385.83 2595.28,1385.83 v1(2607.87,1373.23)
SRAM2_A12: U4.R19 U10.25 | length 1298.1
  Top Layer w5: U4.R19@1740.16,1412.2 U4.R19@1740.16,1413.39 ; U4.R19@1740.16,1412.6 v1@1758.27,1394.49 ; U10.25@2393.31,1327.17 2596.85,1327.17 v1@2642.91,1373.23
  MidLayer2 w5: v1@1757.24,1393.58 1757.24,1393.97 1776.43,1413.16 1810.8,1413.16 1818.34,1420.7 1818.34,1448.26 1838.58,1468.51 2188.58,1468.51 2276.77,1380.32 2458.27,1380.32 2498.03,1420.08 2592.13,1420.08 v1(2639.76,1372.44)
  other v1: 1759.45,1394.09
SRAM2_A13: U4.R26 U10.26 | length 424.7
  Top Layer w5: U4.R26@2015.75,1413.39 2020.08,1417.72 2071.65,1417.72 2077.17,1412.2 2129.13,1412.2 2157.95,1383.39 2171.61,1369.73 2253.36,1369.73 2327.82,1295.27 U10.26@2387.89,1295.27
SRAM2_A14: U4.T24 U10.27 | length 531.4
  Top Layer w5: U4.T24@1937.01,1374.02 v1(1956.69,1354.33) ; v1(2337.4,1241.34) 2359.83,1263.77 U10.27@2387.89,1263.77
  MidLayer3 w5: v1(1956.69,1354.33) 1976.38,1374.02 2008.27,1374.02 2022.29,1360 2218.74,1360 v1(2337.4,1241.34)
SRAM2_A15: U4.AD25 U10.42 | length 805.5
  Top Layer w5: U4.AD25@1976.38,1059.05 1996.06,1039.37 ; 1996.85,1038.58 2036.42,1038.58 2169.25,905.75 2194.25,905.75 2204,896 ; 2204.02,896.02 2308.27,791.76 2308.27,738.58 2337.8,709.06 2411.02,709.06 2427.82,692.26 2444.23,692.26 2453.82,701.85 2458.27,706.3 2458.27,757.87 2424.81,791.33 U10.42@2387.89,791.33
SRAM2_A16: U4.AD26 U10.43 | length 496.1
  Top Layer w5: U4.AD26@2015.75,1059.05 2031.95,1059.05 2175.12,915.87 2199.12,915.87 2355.17,759.83 U10.43@2387.89,759.83
SRAM2_A17: U4.Y23 U10.44 | length 875.2
  Top Layer w5: U4.Y23@1897.64,1216.54 v1(1917.32,1196.85) ; U10.44@2370.09,728.34 U10.44@2387.89,728.34 2419.36,728.34 v1(2434.5,713.2)
  MidLayer2 w5: v1(1917.32,1196.85) 1937.01,1177.17 2007.09,1177.17 2041.83,1142.42 2100.84,1142.42 2438.35,804.91 2438.35,717.05 v1(2434.5,713.2)
SRAM2_A18: U4.T20 U10.28 | length 847.3
  Top Layer w5: U4.T20@1779.53,1374.02 v1(1799.21,1354.33) ; v1(2311.42,1215.75) 2340.55,1215.75 2356.69,1231.89 U10.28@2372.44,1231.89
  MidLayer3 w5: v1@1802.76,1354.33 1822.44,1334.65 1888.58,1334.65 1897.64,1343.7 1897.64,1366.54 1916.14,1385.04 1954.73,1385.04 1983.49,1413.8 2008.66,1413.8 2051.79,1370.67 2241.59,1370.67 2357.82,1254.45 2357.82,1230.66 2342.9,1215.75 v1(2311.42,1215.75)
SRAM2_D0: U4.AA23 U10.7 | length 1074
  Top Layer w5: U4.AA23@1897.64,1177.17 v1(1917.32,1157.48) ; v1(2767.69,917.32) U10.7@2836.71,917.32
  MidLayer1 w5: v1@1916.14,1157.48 1916.73,1156.89 1935.83,1137.8 2004.73,1137.8 2022.12,1120.41 2022.12,1096.18 2090.02,1028.28 2255.18,1028.28 2338.58,944.88 2482.35,944.88 2494.16,956.69 2527.58,956.69 2539.11,968.23 2539.11,968.5 2633.86,968.5 2685.06,917.3 v1@2759.84,917.3
SRAM2_D1: U4.AA25 U10.8 | length 964.4
  Top Layer w5: U4.AA25@1976.38,1177.17 v1(1996.06,1157.48) ; v1(2791.34,948.82) U10.8@2836.71,948.81
  MidLayer1 w5: v1@1995.67,1155.51 v1@1996.06,1155.51 ; v1(1996.06,1157.48) 1999.19,1157.48 2056.56,1100.11 2133.31,1100.11 2189.4,1044.02 2297.64,1044.02 2357.41,984.25 2500,984.25 2515.75,1000 2531.5,1000 2547.24,984.25 2649.61,984.25 2685.04,948.83 v1@2787.41,948.83
SRAM2_D2: U4.Y24 U10.9 | length 989.7
  Top Layer w5: U4.Y24@1937.01,1216.54 v1(1956.69,1196.85) ; v1(2767.69,980.31) U10.9@2836.71,980.31
  MidLayer1 w5: v1(1956.69,1196.85) 1976.38,1177.17 2011.42,1177.17 2045.88,1142.71 2246.19,1142.71 2289.77,1099.13 2441.3,1099.13 2500.34,1040.09 2625.27,1040.09 2685.04,980.32 ; 2685.04,980.29 v1@2759.84,980.29
SRAM2_D3: U4.Y25 U10.10 | length 954.3
  Top Layer w5: U4.Y25@1976.38,1216.54 v1(1996.06,1196.85) ; v1(2787.4,1011.81) U10.10@2836.71,1011.8
  MidLayer1 w5: v1(1996.06,1196.85) 2006.3,1196.85 2029.43,1173.72 2046.53,1173.72 2057.54,1184.74 2084.8,1184.74 2115.35,1154.19 2252.42,1154.19 2295.67,1110.94 2452.06,1110.94 2496.06,1066.93 2629.92,1066.93 2685.03,1011.82 v1(2787.4,1011.81)
SRAM2_D4: U4.V22 U10.13 | length 1090.3
  Top Layer w5: U4.V22@1858.27,1295.28 v1(1877.95,1275.59) ; v1(2759.84,1106.3) U10.13@2836.71,1106.29
  MidLayer1 w5: v1(1877.95,1275.59) 1897.64,1255.91 1897.64,1226.38 1906.69,1217.32 1907.48,1216.54 2073.96,1216.54 2125.7,1164.8 2271.62,1164.8 2314.37,1122.05 2484.25,1122.05 2519.68,1086.62 2555.11,1086.62 2574.79,1106.31 v1(2759.84,1106.3)
SRAM2_D5: U4.V24 U10.14 | length 983.3
  Top Layer w5: U4.V24@1937.01,1295.28 v1(1956.69,1275.59) ; v1(2787.4,1137.8) U10.14@2836.71,1137.79
  MidLayer1 w5: v1@1956.69,1273.62 v1(1956.69,1275.59) 1976.18,1256.1 2051.37,1256.1 2089.16,1218.32 ; 2089.03,1218.19 2132.37,1174.86 2285.97,1174.86 2328.14,1132.68 2501.18,1132.68 2515.75,1118.11 2531.49,1118.11 2551.17,1137.8 ; 2551.17,1137.8 v1(2787.4,1137.8)
SRAM2_D6: U4.V25 U10.15 | length 943.2
  Top Layer w5: U4.V25@1976.38,1295.28 v1@1996.06,1275.59 ; v1(2759.84,1169.29) U10.15@2836.71,1169.28
  MidLayer1 w5: v1@1996.07,1275.59 v1(1996.46,1275.59) 2046.03,1275.59 2106.38,1215.24 2271.07,1215.24 2320.95,1165.36 2523.61,1165.36 2539.36,1149.61 2555.11,1149.61 2592.11,1186.61 2742.52,1186.61 v1(2759.84,1169.29)
SRAM2_D7: U4.U22 U10.16 | length 1034.8
  Top Layer w5: U4.U22@1858.27,1334.65 v1(1877.95,1314.96) ; v1(2787.4,1200.79) U10.16@2836.71,1200.78
  MidLayer1 w5: v1@1877.56,1315.75 1877.95,1315.35 v1(1877.95,1314.96) 1897.64,1295.27 2040.49,1295.27 2074.66,1261.1 2479.08,1261.1 2508.22,1231.97 2717.15,1231.97 2748.31,1200.8 v1(2787.4,1200.79)
SRAM2_D8: U4.U20 U10.29 | length 693.6
  Top Layer w5: U4.U20@1779.53,1334.65 v1(1799.21,1314.96) ; v1@2335.43,1187.8 2336.81,1189.17 2348.42,1200.78 U10.29@2387.89,1200.78
  MidLayer4 w5: v1(1799.21,1314.96) 1799.61,1314.96 1819.29,1295.28 2039.5,1295.28 2167.75,1167.02 2314.27,1167.02 v1(2336.61,1189.37)
SRAM2_D9: U4.U24 U10.30 | length 622.7
  Top Layer w5: U4.U24@1937.01,1334.65 v1(1956.69,1314.96) ; v1(2061.02,1305.12) 2073.38,1317.48 ; 2073.29,1317.58 2098.87,1343.16 2248.44,1343.16 2288.78,1302.82 2288.78,1194.58 2314.08,1169.28 U10.30@2387.89,1169.28
  MidLayer2 w5: v1(1956.69,1314.96) 1976.58,1295.08 2050.98,1295.08 v1(2061.02,1305.12)
SRAM2_D10: U4.U23 U10.31 | length 643.5
  Top Layer w5: U4.U23@1897.64,1334.65 v1(1917.32,1314.96) ; v1(2221.87,1321.51) 2274.02,1269.36 2274.02,1189.66 2325.89,1137.79 U10.31@2387.89,1137.79
  MidLayer3 w5: v1@1918.11,1314.96 1937.8,1334.65 2005.39,1334.65 2016.86,1346.11 2197.27,1346.11 v1(2221.87,1321.51)
SRAM2_D11: U4.V23 U10.32 | length 633.7
  Top Layer w5: U4.V23@1897.64,1295.28 v1(1917.32,1275.59) ; v1(2221.87,1281.17) 2258.02,1245.02 2258.02,1174.66 2326.39,1106.29 U10.32@2387.89,1106.29
  MidLayer3 w5: v1(1917.32,1275.59) 1917.32,1270.84 1932.58,1255.58 2012.28,1255.58 2037.86,1281.17 v1(2221.87,1281.17)
SRAM2_D12: U4.V21 U10.35 | length 870.6
  Top Layer w5: U4.V21@1818.9,1295.28 v1(1838.58,1275.59) ; v1(2186.45,1320.53) 2201.21,1305.77 2201.21,1068.62 2258.03,1011.8 U10.35@2387.89,1011.8
  MidLayer3 w5: v1(1838.58,1275.59) 1838.58,1276.72 1856.81,1294.94 2005.39,1294.94 2039.83,1329.38 2177.59,1329.38 v1(2186.45,1320.53)
SRAM2_D13: U4.W23 U10.36 | length 751.1
  Top Layer w5: U4.W23@1897.64,1255.91 v1(1917.32,1236.22) ; v1(2099.86,1304.78) 2189.56,1215.08 2189.56,1061.74 2270.99,980.31 U10.36@2387.89,980.31
  MidLayer2 w5: v1(1917.32,1236.22) 1917.32,1236.4 1936.51,1255.58 2008.34,1255.58 2028.02,1275.26 2070.34,1275.26 v1(2099.86,1304.78)
SRAM2_D14: U4.W21 U10.37 | length 726.8
  Top Layer w5: U4.W21@1818.9,1255.91 v1(1838.58,1236.22) ; v1(2073.29,1162.1) 2123.74,1111.66 2123.74,1089.39 2264.32,948.81 U10.37@2387.89,948.81
  MidLayer3 w5: v1(1838.58,1236.22) 1858.27,1216.54 2046.41,1216.54 2073.29,1189.66 v1(2073.29,1162.1) v1@2074.27,1163.09
SRAM2_D15: U4.Y22 U10.38 | length 678.8
  Top Layer w5: U4.Y22@1858.27,1216.54 v1(1877.95,1196.85) ; v1(2074.27,1120.78) 2100.01,1095.04 2100.01,1051.99 2190,962 2222,962 2266.68,917.32 U10.38@2387.89,917.32
  MidLayer3 w5: v1(1877.95,1196.85) 1897.64,1177.17 2017.88,1177.17 v1(2074.27,1120.78)
SRAM2_NBHE: U4.AB26 U10.40 | length 508.9
  Top Layer w5: U4.AB26@2012.6,1137.4 2013.98,1136.02 2034,1116 2034,1088 2185.87,936.13 2208.7,936.13 2290.51,854.32 U10.40@2387.89,854.32
SRAM2_NBLE: U4.AA24 U10.39 | length 583.5
  Top Layer w5: U4.AA24@1937.01,1177.17 v1(1956.69,1157.48) ; v1(2075.26,1079.45) 2075.37,1080.65 2075.37,1079.45 2075.37,1061.63 2190.87,946.13 2218.87,946.13 2279.18,885.82 U10.39@2387.89,885.82
  MidLayer3 w5: v1@1957.48,1157.48 1977.17,1137.8 2016.91,1137.8 v1(2075.26,1079.45)
SRAM2_NCS: U4.AB24 U10.6 | length 1009.9
  Top Layer w5: U4.AB24@1937.01,1137.8 v1(1956.69,1118.11) ; v1(2791.34,885.83) U10.6@2836.71,885.82
  MidLayer1 w5: v1(1956.69,1118.11) 1976,1098.8 2003.8,1098.8 2147.6,955 2273.35,955 2303.15,925.2 2503.93,925.2 2515.75,937.01 2531.5,937.01 2543.31,925.2 2645.67,925.2 2685.03,885.83 v1@2787.41,885.83
SRAM2_NOE: U4.AC26 U10.41 | length 491.1
  Top Layer w5: U4.AC26@2015.75,1098.42 2015.75,1090.25 2179.87,926.13 2204,926.13 2307.3,822.83 U10.41@2387.89,822.83
SRAM2_NWE: U4.T17 U10.17 | length 1273.4
  Top Layer w5: v1(1642.13,1356.3) 1661.02,1374.02 U4.T17@1661.42,1374.02 ; v1(2759.84,1232.28) U10.17@2836.71,1232.28
  MidLayer1 w5: v1(1642.13,1356.3) 1660.24,1334.65 2114.27,1334.65 2148.07,1300.85 2514.12,1300.85 2544.62,1270.34 2721.78,1270.34 v1(2759.84,1232.28)
STATUS_LED: NT6.1 U2.2 | length 74.7
  Bottom Layer w5: U2.2@1397.64,207.68 U2.2@1397.63,220.47 1397.64,251.97 1404.53,258.86 NT6.1@1425.2,258.86
SUSPEND: R9.2 U4.V20 | length 2715.1
  Top Layer w5: U4.V20@1779.53,1295.28 v1(1799.21,1275.59)
  MidLayer3 w5: v1(727.18,2842.78) 678.96,2794.56 678.96,2320.27 1054.85,1944.38 1134.55,1944.38 1153.36,1925.57 1295.81,1925.57 1295.93,1925.69 1296.91,1925.69 1306.9,1915.7 1306.9,1500.45 1331.35,1476 1449.2,1476 1464.57,1460.63 1464.57,1185.04 1472.44,1177.17 1527.56,1177.17 1539.37,1188.98 1539.37,1283.46 1550.85,1294.94 1780.06,1294.94 v1@1799.21,1275.79
  Bottom Layer w5: v1(727.18,2842.78) v1@732.1,2837.86 ; v1@733.08,2837.86 736.03,2834.9 R9.2@736.03,2811.81
SW0: HDR_B1.42 U4.AA9 | length 1010.1
  Top Layer w5: v1(1326.77,1157.48) U4.AA9@1346.46,1177.17
  MidLayer2 w5: v1(1326.77,1157.48) 1307.46,1138.17 1307.46,780.85 1308,780.31 1308,741 1340,709 1548,709 1578.47,739.47 1674.31,739.47 1691.79,721.99 1691.79,703.49 v2(1728.35,666.93)
  Bottom Layer w7.87: v2(1728.35,666.93) 1751.97,643.31 HDR_B1.42@1751.97,606.3
SW1: HDR_B1.44 U4.AF17 | length 425.8
  Top Layer w5: U4.AF17@1661.42,980.31 1661.42,883.41 1673,871.82 1673,758 1684,747 ; 1683.85,746.85 v2(1725.2,705.51)
  Bottom Layer w7.87: v2(1725.2,705.51) 1783.46,647.24 HDR_B1.44@1783.47,606.3 HDR_B1.44@1783.01,607.51
SW2: HDR_B1.46 U4.AD9 | length 855.8
  Top Layer w5: v1(1326.77,1039.37) U4.AD9@1346.46,1059.05
  MidLayer2 w5: v1(1326.77,1039.37) 1326.77,978.74 1363.82,941.69 1363.82,815.74 1381.54,798.02 1421.88,798.02 1462.22,757.68 1541.93,757.68 1549.8,749.81 1682.08,749.81 1706.3,725.59 1733.07,725.59 1747.64,711.02 1747.64,687.8 1773.62,661.81 1811.42,661.81 v2(1814.96,665.35)
  Bottom Layer w7.87: HDR_B1.46@1814.96,606.3 v2(1814.96,665.35)
SW3: HDR_B1.48 U4.AD10 | length 801.2
  Top Layer w5: v1(1366.14,1039.37) U4.AD10@1385.83,1059.05
  MidLayer2 w5: v1@1364,1039 1364.89,1038.11 1374,1029 1374,904.01 1476.05,801.96 1567.51,801.96 1609.23,760.24 1687,760.24 1711.41,735.83 1780.71,735.83 v2(1811.81,704.72)
  Bottom Layer w7.87: v2@1811.02,705.51 v2(1811.81,704.72) 1846.46,670.08 HDR_B1.48@1846.46,606.3
SW4: HDR_B1.50 U4.AF22 | length 389.7
  Top Layer w5: U4.AF22@1858.27,980.31 1858.27,956.69 1887.01,927.95 1887.01,674.41 v2(1877.95,665.35)
  Bottom Layer w7.87: HDR_B1.50@1877.95,606.3 v2(1877.95,665.35)
TCK: R4.2 U4.A25 | length 517.1
  Top Layer w5: U4.A25@1976.38,1964.57 2055.28,2043.47 2055.28,2098.18 v1(2126.1,2169)
  Bottom Layer w5: v1(2126.1,2169) 2147.1,2148 2183,2148 2219.8,2184.8 2307.66,2184.8 R4.2@2339.62,2216.76
TDI: R6.2 U4.G7 | length 971.8
  Top Layer w5: v1(1248.03,1748.03) U4.G7@1267.72,1728.35
  MidLayer1 w5: v1(632.4,2191.6) 632.4,2162.48 641.73,2153.15 668.9,2153.15 895.67,1926.38 1100,1926.38 1111,1915.38 1111,1894 1118.78,1886.22 1138.78,1886.22 1149,1876 1149,1875.02 ; 1149.98,1875.02 1149.98,1816.02 1159,1807 1218.49,1807 1228.49,1797 1228.49,1767.57 v1(1248.03,1748.03)
  Bottom Layer w5: v1(632.4,2191.6) 637.9,2197.1 665.3,2197.1 675.08,2187.32 R6.2@689.74,2187.32
TDO: R5.2 U4.E23 | length 672.6
  Top Layer w5: U4.E23@1897.64,1807.09 v1(1917.32,1826.77)
  MidLayer1 w5: v1(1917.32,1826.77) 1936.84,1846.28 1964.48,1846.28 1976,1857.8 1976,1958.39 2084,2066.38 v1(2084,2169)
  Bottom Layer w5: v1@2084,2170 2084.5,2169.5 2105,2149 2105,2120 2117.41,2107.59 2198.22,2107.59 R5.2@2240.8,2150.17
TMS: R3.2 U4.D4 | length 1558.6
  Top Layer w5: U4.D4@1149.61,1846.46 1149.61,1846.61 v1(1169.65,1866.65) v1@1171,1868
  MidLayer1 w5: v1@1085,2166 1085.5,2165.5 1127,2124 1127,1941 1150,1918 1150,1895 1169.65,1875.35 v1(1169.65,1866.65)
  Bottom Layer w5: v1@1084,2164 v1(1085.14,2165.14) 1149.66,2229.66 1833.66,2229.66 1839,2235 2144,2235 2162.24,2216.76 R3.2@2240.87,2216.76
TOFF: R23.1 U6.7 | length 159.5
  Top Layer w15.75: U6.7@2824.58,1783.25 2824.8,1783.46 2874.02,1783.46 2905.51,1814.96 R23.1@2970.94,1814.96
VFILT: C110.1 C111.1 R19.2 U6.5 U6.12 | length 544.3
  Top Layer w15.75: R19.2@2492.12,1643.22 2492.12,1688.98 C111.1@2488.19,1692.91 2488.19,1716.54 2504.9,1733.25 U6.12@2592.58,1733.25 ; U6.12@2592.58,1733.25 U6.5@2824.58,1733.25 2904.53,1733.27 2918.31,1719.48 C110.1@2944.88,1719.48
VSET: R18.1 R25.1 U7.5 | length 153
  Top Layer w5: R18.1@1847.95,2358.26 1870.07,2358.26 1875.51,2363.7 R25.1@1875.51,2413.38 1875.51,2462.12 1881.89,2468.5 U7.5@1897.64,2468.5
pads on no net: HDR_B1.93 HDR_B1.95 HDR_B1.MH5 HDR_B1.MH6 HDR_L1.MH5 HDR_L1.MH6 HDR_T1.95 HDR_T1.MH5 HDR_T1.MH6 MH1.MOUNT MH2.MOUNT MH3.MOUNT U1.5 U2.1 U3.A1 U3.A8 U3.B1 U3.B4 U3.C1 U3.D1 U3.E1 U3.F8 U3.G1 U3.G8 U3.H1 U3.H8 U4.A5 U4.A7 U4.A13 U4.A17 U4.A23 U4.A24 U4.AA4 U4.AA8 U4.AA19 U4.AA20 U4.AB3 U4.AB4 U4.AB10 U4.AB17 U4.AB20 U4.AC5 U4.AC7 U4.AC17 U4.AC18 U4.AD5 U4.AD16 U4.AD23 U4.AF2 U4.AF7 U4.B24 U4.B25 U4.B26 U4.C1 U4.C2 U4.C4 U4.D1 U4.D2 U4.D5 U4.D7 U4.D12 U4.D14 U4.D15 U4.D19 U4.E6 U4.E9 U4.E11 U4.E18 U4.E20 U4.F9 U4.F10 U4.F18 U4.FID1 U4.G1 U4.G2 U4.G5 U4.G11 U4.G14 U4.G16 U4.G18 U4.G25 U4.G26 U4.H4 U4.H13 U4.H18 U4.H23 U4.H24 U4.H25 U4.H26 U4.J1 U4.J2 U4.J3 U4.J10 U4.J13 U4.J15 U4.J17 U4.K1 U4.K24 U4.L10 U4.L23 U4.M10 U4.M24 U4.N23 U4.N25 U4.N26 U4.P10 U4.R17 U4.R23 U4.R24 U4.U3 U4.U25 U4.U26 U4.V4 U4.V26 U4.W1 U4.W2 U4.W18 U4.W25 U4.W26 U4.Y3 U4.Y4 U4.Y8 U4.Y11 U4.Y16 U4.Y18 U4.Y19 U4.Y26 U5.1 U8.40 U9.40
copper on no net: | length 1092.4
  Top Layer w5: v1@1052.36,1867.32 1070.87,1885.83 ; v1(1070.83,946.26) 1070.83,979.72 ; 1070.87,1728.35 1070.87,1730.08 ; 1070.87,1846.46 v1@1090.16,1865.75 ; 1071.85,1729.36 1071.89,1729.32 ; 1110.24,1137.8 1110.63,1137.8 1110.63,1138.19 v1(1129.92,1157.48) 1149.61,1177.17 ; v1(1129.92,1196.85) 1149.61,1216.53 ; 1148.07,1885.83 1149.61,1885.83 ; v1(1169.29,1748.03) 1188.98,1728.35 ; 1188.98,1098.42 v1(1169.29,1078.74) 1188.98,1059.05 1189.66,1058.37 1189.66,1057.8 ; 1189.75,1845.68 1188.98,1846.46 1208.72,1826.72 1228.35,1807.09 ; v1(1248.03,1078.74) 1267.72,1098.42 ; v1(1248.03,1984.25) 1267.72,1964.57 ; 1307.08,1177.17 v1(1287.4,1196.85) 1307.09,1216.53 ; v1(1326.77,1787.4) 1346.46,1767.72 ; v1(1326.77,1826.77) 1346.46,1807.09 ; v1(1366.14,1118.11) 1385.83,1137.79 ; v1(1366.14,1787.4) 1385.83,1767.72 ; v1(1405.51,1196.85) 1425.2,1216.53 ; 1582.68,1846.46 1582.68,1846.85 ; 1622.05,1728.35 v1(1641.73,1748.03) ; 1661.42,1135.83 1661.42,1137.34 1661.42,1137.8 ; 1700.79,1216.54 v1(1720.47,1196.85) ; 1700.79,1255.91 v1(1720.47,1236.22) 1740.16,1216.54 ; 1700.79,1728.35 v1(1720.47,1748.03) 1700.79,1767.72 ; v1@1720.99,1197.76 1721.39,1197.76 1740.16,1216.53 ; v1(1759.84,1196.85) 1740.16,1216.54 ; 1779.53,1807.09 v1(1799.21,1826.77) ; 1897.64,1688.98 v1(1917.32,1708.66) ; 1937.01,1964.57 v1(1956.69,1984.25) ; 1938.87,1922.72 1939.49,1922.72 ; 1976.38,1255.91 v1(1996.06,1236.22) ; v1@1996.46,1747.64 1996.85,1747.24 2015.75,1728.35 ; 2015.75,1255.91 2021.65,1255.91 v1(2040.94,1236.61)
  Top Layer w7.87: 3149.61,4212.6 3149.61,4330.71
  Top Layer w10: v1@1697.34,2158.37 v1@1698.62,2159.65 ; v1(2526.38,1557.09) v1@2526.77,1556.69
  Bottom Layer w10: v1@2040.55,1238.58 2041.73,1237.4 v1@2044.88,1234.25
  Bottom Layer w11.81: v1(1248.03,1984.25) v1@1249.02,1985.24
  Bottom Layer w12: v1(1917.32,1708.66) v1@1918.31,1709.65
  other v1: 1618.11,43.31 157.48,59.06 275.59,59.06 393.7,59.06 511.81,59.06 629.92,59.06 748.03,59.06 866.14,59.06 984.25,59.06 1102.36,59.06 1220.47,59.06 1338.58,59.06 1456.69,59.06 1771.65,59.06 1889.76,59.06 2007.87,59.06 2125.98,59.06 2244.09,59.06 2362.2,59.06 2480.31,59.06 2598.43,59.06 2716.54,59.06 2834.65,59.06 2952.76,59.06 3070.87,59.06 1556.86,68.68 1679.36,68.68 59.06,118.11 3169.29,118.11 1531.5,129.92 1704.72,129.92 1556.86,191.17 1679.36,191.17 1618.11,216.54 59.06,236.22 3169.29,236.22 59.06,354.33 3169.29,354.33 59.06,472.44 3169.29,472.44 59.06,590.55 3169.29,590.55 59.06,708.66 3169.29,708.66 59.06,826.77 3169.29,826.77 59.06,944.88 3169.29,944.88 59.06,1062.99 3169.29,1062.99 59.06,1181.1 3169.29,1181.1 59.06,1299.21 3169.29,1299.21 59.06,1417.32 3169.29,1417.32 2622.05,1484.25 59.06,1535.43 3169.29,1535.43 59.06,1653.54 3169.29,1653.54 1997.64,1748.03 59.06,1771.65 1209,1827 1051.57,1866.14 1090.94,1866.54 59.06,1889.76 3169.29,1889.76 59.06,2007.87 3169.29,2007.87 59.06,2125.98 3169.29,2125.98 1660.01,2159.88 1698.03,2160.24 1659.02,2196.29 59.06,2244.09 3169.29,2244.09 59.05,2362.2 3169.29,2362.2 59.05,2480.32 3169.29,2480.32 59.06,2598.43 3169.29,2598.43 59.06,2716.54 3169.29,2716.54 59.06,2834.65 3169.29,2834.65 59.06,2952.76 3169.29,2952.76 59.06,3070.87 3169.29,3070.87 59.06,3188.98 3169.29,3188.98 59.06,3307.09 3169.29,3307.09 59.06,3425.2 3169.29,3425.2 59.06,3543.31 3169.29,3543.31 59.06,3661.42 3169.29,3661.42 59.06,3779.53 3169.29,3779.53 59.06,3897.64 3169.29,3897.64 59.06,4015.75 3169.29,4015.75 157.48,4094.49 275.59,4094.49 2952.76,4094.49 3070.87,4094.49 354.33,4145.67 2874.02,4145.67 446,4200.8 564.11,4200.8 682.22,4200.8 800.33,4200.8 905.51,4200.79 1023.62,4200.79 1141.73,4200.79 1259.84,4200.79 1614.17,4200.79 1732.28,4200.79 1850.39,4200.79 1968.5,4200.79 2086.61,4200.79 2204.72,4200.79 2322.83,4200.79 2440.94,4200.79 2559.06,4200.79 2677.17,4200.79 2795.28,4200.79 129.92,4240.16 3106.3,4240.16 68.68,4265.53 191.17,4265.53 3045.05,4265.53 3167.54,4265.53 43.31,4326.77 216.54,4326.77 3019.68,4326.77 3192.91,4326.77 68.68,4388.02 191.17,4388.02 3045.05,4388.02 3167.54,4388.02 129.92,4413.39 3106.3,4413.39

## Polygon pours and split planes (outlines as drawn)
2V5 on Top Layer "Top Layer-2V5" (solid, remove dead copper, pour order 1002): 1716.1,2476.73 1803.67,2476.73 1809.58,2470.82 1809.58,2379.31 1816.46,2372.42 1816.46,2167.75 1800.72,2152.01 1796.78,2148.07 1616.71,2148.07 1602.94,2161.85 1602.94,2383.25 1696.42,2476.73
AGND on Top Layer "Top Layer-AGND" (solid, remove dead copper, pour order 1003): 2465.9,2060.5 3037.61,2060.5 3072.05,2026.06 3072.05,1665.91 3039.58,1633.44 2393.09,1633.44 2373.41,1653.12 2373.41,2011.3 2423.59,2061.48
GND on Top Layer "Top Layer-GND 1" (solid, remove dead copper, pour order 1004): 382.78,4258.75 2892.96,4258.75 2965.78,4185.94 3010.06,4141.66 3148.8,4141.66 3195.05,4095.41 3195.05,56.09 3165.53,26.57 1784.98,26.57 1759.39,52.15 1759.39,235.18 1742.66,251.9 1487.81,251.9 1475.02,239.11 1475.02,31.49 1459.27,15.74 43.3,15.74 27.55,31.49 27.55,4085.57 105.29,4163.3 267.65,4163.3 363.1,4258.75
GND on MidLayer1 "GND-LAYER1" (solid, remove dead copper, pour order 1000): 35.43,35.43 35.43,185.04 35.43,4015.75 409.45,4389.76 421.26,4401.57 657.48,4401.57 2830.71,4401.57 3196.85,4035.43 3196.85,3811.02 3196.85,35.43
1V2 on MidLayer2 "MidLayer2-1V2" (solid, remove dead copper, pour order 1005): 1676.74,2176.61 1936.51,2176.61 1987.68,2125.44 1987.68,1142.42 1951.27,1106.02 1278.22,1106.02 1264.44,1119.79 1264.44,1855.82 1584.24,2175.62
GND on MidLayer2 "MidLayer2-GND 1" (solid, remove dead copper, pour order 1006): 393.6,4291.22 2968.73,4291.22 3189.14,4070.81 3189.14,68.88 3163.56,43.3 59.04,43.3 28.54,73.8 28.54,4057.03 262.73,4291.22
GND on MidLayer3 "GND-LAYER3" (solid, remove dead copper, pour order 1001): 35.43,35.43 3196.85,35.43 3196.85,279.53 3196.85,4007.87 2803.15,4401.57 2590.55,4401.57 425.2,4401.57 35.43,4011.81
GND on MidLayer4 "MidLayer4-GND 1" (solid, remove dead copper, pour order 1008): 410.33,4314.84 2890.99,4314.84 3198,4007.83 3198,83.64 3162.58,48.22 3147.82,33.46 79.7,33.46 45.26,67.9 45.26,4049.16 310.94,4314.84
1V2 on MidLayer4 "MidLayer4-1V2 1" (solid, remove dead copper, pour order 1007): 1122.53,2152.01 3105.72,2152.01 3143.88,2120.52 3143.88,757.68 3098.56,720.29 900.72,720.29 724.22,865.92 724.22,2043.77 855.4,2152.01
2V5 on Bottom Layer "Bottom Layer-2V5 1" (solid, remove dead copper, pour order 1009): 980.06,2238.6 2524.94,2238.6 2555.45,2208.1 2555.45,718.32 2523.96,686.83 844.27,686.83 785.23,745.87 785.23,2067.38 956.45,2238.6
GND on Bottom Layer "Bottom Layer-GND 1" (solid, remove dead copper, pour order 1010): 45.26,4013.74 45.26,111.19 107.26,49.2 3131.09,49.2 3181.27,99.38 3181.27,4026.53 2803.42,4404.38 473.3,4404.38
GND on GND-Layer5 (split plane): 1523.62,4436.6 3216.12,4436.6 3216.12,20.1 20.1,20.1 20.1,4436.6 1523.62,4436.6
3V3 on VCC (split plane): 2701.84,4061.24 2702.17,4058.67 2703.17,4056.27 2704.74,4054.22 2720.98,4037.98 2721.87,4037.3 2723.04,4036.4 2725.43,4035.41 2728,4035.07 3041.89,4035.07 3106.07,3970.89 3106.07,2319.11 3064.6,2277.64 2921.43,2277.64 2802.3,2396.78 2800.24,2398.36 2797.84,2399.35 2795.28,2399.69 2629.92,2399.69 2627.35,2399.35 2624.96,2398.36 2622.9,2396.78 2617,2390.88 2615.42,2388.82 2614.43,2386.43 2614.09,2383.86 2614.09,2206.87 2429.99,2022.77 2428.41,2020.71 2427.42,2018.32 2427.08,2015.75 2427.08,1590.55 2427.42,1587.98 2428.41,1585.59 2429.99,1583.53 2445.74,1567.78 2447.79,1566.21 2450.19,1565.21 2452.76,1564.88 2582.68,1564.88 2585.25,1565.21 2587.64,1566.21 2589.7,1567.78 2618.29,1596.37 2712.19,1596.37 2725.07,1583.49 2725.07,1440 2725.41,1437.43 2726.4,1435.04 2727.98,1432.98 2732.98,1427.98 2735.04,1426.4 2737.43,1425.41 2740,1425.07 3005.77,1425.07 3045.19,1385.65 3045.19,1287.4 3045.19,1244.09 3045.19,795.45 2948.64,698.9 2838.58,698.9 2836.01,698.57 2833.62,697.57 2831.56,696 2780.38,644.82 2778.8,642.76 2777.81,640.36 2777.47,637.8 2777.47,523.8 2617,363.32 2615.42,361.26 2614.43,358.87 2614.09,356.3 2614.09,40.66 42.65,40.66 40.66,42.65 40.66,621.47 41.48,623.01 42.33,625.84 42.62,628.78 42.62,4330.71 129.92,4330.71 129.92,4417.85 2701.84,4417.85
5V0 on VCC (split plane): 3102.36,4334.65 3195.72,4334.65 3195.72,40.66 2633.94,40.66 2633.94,352.19 2794.42,512.67 2796,514.72 2796.99,517.12 2797.33,519.68 2797.33,633.68 2842.69,679.05 2952.76,679.05 2955.33,679.39 2957.72,680.38 2959.78,681.96 3062.14,784.32 3063.03,785.48 3063.72,786.37 3064.01,787.08 3064.71,788.77 3065.05,791.34 3065.05,1244.09 3065.05,1287.4 3065.05,1389.76 3064.71,1392.33 3063.72,1394.73 3062.82,1395.89 3062.14,1396.78 3016.9,1442.02 3014.85,1443.6 3012.45,1444.59 3009.88,1444.93 2744.93,1444.93 2744.93,1587.6 2744.59,1590.17 2743.6,1592.56 2742.02,1594.62 2723.32,1613.32 2721.26,1614.9 2718.87,1615.89 2716.3,1616.23 2614.17,1616.23 2611.6,1615.89 2609.21,1614.9 2607.15,1613.32 2578.57,1584.73 2456.87,1584.73 2446.94,1594.66 2446.94,2011.64 2631.04,2195.74 2632.61,2197.79 2633.6,2200.19 2633.94,2202.76 2633.94,2379.75 2634.03,2379.84 2791.16,2379.84 2910.3,2260.7 2911.2,2260.01 2912.36,2259.12 2914.75,2258.13 2917.32,2257.79 3068.72,2257.79 3071.29,2258.13 3073.68,2259.12 3075.74,2260.7 3123.02,2307.98 3124.6,2310.04 3125.59,2312.43 3125.93,2315 3125.93,3975 3125.59,3977.57 3124.6,3979.96 3123.7,3981.13 3123.02,3982.02 3053.02,4052.02 3050.96,4053.6 3048.57,4054.59 3046,4054.93 2732.11,4054.93 2721.69,4065.35 2721.69,4417.85 3102.36,4417.85
no net on VCC (split plane): 20.1,4435.96 20.1,4436.6 20.74,4436.6
no net on VCC (split plane): 20.58,20.1 20.1,20.1 20.1,20.58

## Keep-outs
Bottom Layer:
  rectangle: 1310.91,4194.61 1507.76,4289.09
  rectangle: 255.91,3149.61 452.76,3244.09
  rectangle: 2643.7,3334.65 2840.55,3417.32
Keep-Out Layer:
  circle w15.75: c2928.82,472.44 r118.11
  circle w15.75: c857.95,472.44 r118.11
  circle w15.75: c306.77,437.01 r118.11
  circle w15.75: c306.77,2507.87 r118.11
  circle w15.75: c857.95,2472.44 r118.11
  circle w15.75: c2928.82,2472.44 r118.11
  region: 0,4456.69 0,4433.07 3236.22,4433.07 3236.22,4456.69
  rectangle: 0,0 3236.22,23.62
  rectangle: 0,0 23.62,4456.69
  region: 3236.22,4456.69 3212.6,4456.69 3212.6,0 3236.22,0
Mechanical 4:
  rectangle: 236.22,4358.27 925.2,4456.69

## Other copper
Top Layer:
  rectangle net GND: 3011.81,1366.15 3031.49,1405.52
  rectangle net 5V0: 2839.82,1449.65 2955.14,1558.01
  rectangle net 5V0: 2885.41,1496.66 3016.97,1700.34
  rectangle net AGND: 2515.6,1915.2 2523.6,1942.4
  region net LX: 2768.7,1716.54 2645.67,1716.54 2645.67,1622.32 2768.7,1622.32
  rectangle net 5V0: 2645.67,2251.97 2740.16,2393.7
  rectangle net GND: 2645.67,2551.18 2740.16,2692.91
  rectangle net GND: 3093.5,1773.6 3142.6,1785.4
  rectangle net 3V3: 2850.39,2100 3027.56,2195
  pour cut-out: 2039.41,956.65 2039.41,1984.21 2039.37,1984.25 1009.41,1984.25 1009.29,1984.37 1009.29,958.11 1007.87,956.69
  pour cut-out: 2554.02,3195 2554.02,2865 2194.02,2865 2194.02,3195
MidLayer4:
  rectangle net 5V0: 2625,2240 2755,2370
